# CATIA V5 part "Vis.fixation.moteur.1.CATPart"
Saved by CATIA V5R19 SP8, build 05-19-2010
Part number: Vis.fixation.moteur.1
Bounding box of the stored display mesh (mm): x 13.5 to 16.5, y -17 to -11, z -1.5 to 1.5
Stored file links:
  G:\EU_thinkMotion\CFAO_2010\MMS_groupe3\MMS_groupe3\jbonnamy\jbonnamy_cfao\Vis.fixation.moteur.1.CATPart
  C:\Users\Micheline\Desktop\projet CFAO\Nouveau dossier\temp\Nouveau dossier\Vis.fixation.CATPart
  G:\EU_thinkMotion\CFAO_2010\MMS_groupe3\MMS_groupe3\jbonnamy\jbonnamy_cfao\jbonnamy_suspension.arriere.directionnelle.CATProduct
  G:\EU_thinkMotion\CFAO_2010\MMS_groupe3\MMS_groupe3\jbonnamy\jbonnamy_cfao\Moteur.CATPart
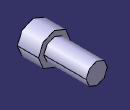
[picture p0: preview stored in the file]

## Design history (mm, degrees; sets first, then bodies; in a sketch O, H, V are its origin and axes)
External parameters (linked from other documents)
  External.Epaisseur.support.10 = 1.5 mm
  External.Diametre.vis.fixation = 2 mm
Set1
  DatumSurface1: linked copy from another document
Body1 (main body)
  Sketch1 on DatumSurface1, origin (15, -15, 0), H (1, 0, 0), V (0, 0, 1)
    circle A1 centre (0, 0) radius 1
    radius A1 = 1 {= External.Diametre.vis.fixation /2}
  Pad1: profile Sketch1, direction (0, 1, 0), length 4 {= 2*External.Epaisseur.support.10 +1mm}
  Sketch2 on DatumSurface1, origin (15, -15, 0), H (1, 0, 0), V (0, 0, 1)
    circle A1 centre (0, 0) radius 1.5
    radius A1 = 1.5 {= 3*External.Diametre.vis.fixation /4}
  Pad2: profile Sketch2, direction (0, -1, 0), length 2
